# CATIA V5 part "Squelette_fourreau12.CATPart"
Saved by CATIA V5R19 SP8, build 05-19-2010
Part number: Squelette_fourreau12
Bounding box of the stored display mesh (mm): x 10 to 30, y 20 to 20, z -30 to 20
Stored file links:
  G:\EU_thinkMotion\CFAO_2010\MMS_groupe2\MMS_groupe2\A reprendre\jcauchy\Squelette_fourreau12.CATPart
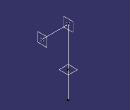
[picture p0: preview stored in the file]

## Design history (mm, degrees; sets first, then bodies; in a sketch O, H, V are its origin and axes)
Parameters
  Longueur_fourreau12 = 50 mm
  Longueurtige_fourreau12 = 30 mm
  Longueurfixation_fourreau12 = 20 mm
Set1
  Point1: (10, 20, 20)
  Point2: (30 {= 10mm+Longueurfixation_fourreau12}, 20, 20)
  Line1: type PtPt, FirstPoint Point1, SecondPoint Point2
  Plane1: type Normal, Curve Line1, RefPoint Point2
  Plane2: type Normal, Curve Line1, RefPoint Point1
  Point3: type OnCurve, Support Line1, Length 20 {= Longueurfixation_fourreau12}
  Line2: type Angle, RefPoint Point1, Curve Line1, Support zx-plane, Start 0, End 30 {= Longueurtige_fourreau12}, Angle 90
  Plane3: type Normal, Curve Line2, RefPoint vertex of Line2
  Line3: type Normal, RefPoint vertex of Line2, RefSkin Plane3, Start 0, End 20 {= Longueur_fourreau12 -Longueurtige_fourreau12}
Body1 (main body)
